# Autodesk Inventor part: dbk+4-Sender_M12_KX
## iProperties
Created: 2010-01
Part Number: dbk+4-Sender_M12_KX
Document SubType Name: Modeling
Designer: Oliver Liedtke
Density: 1 g/cm^3
Author: Oliver Liedtke
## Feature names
1. Umdrehung1 [Revolution]
2. Extrusion1
